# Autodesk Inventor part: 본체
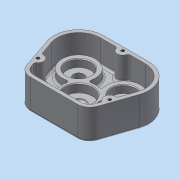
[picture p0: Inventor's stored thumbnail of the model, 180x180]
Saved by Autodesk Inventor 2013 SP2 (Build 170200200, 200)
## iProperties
Created: 2014-12
Part Number: 본체
Material: 알루미늄 6061
Document SubType Name: Modeling
Designer: dgall
Density: 2.71 g/cm^3
Author: dgall
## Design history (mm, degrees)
sketch "스케치1"
  geometry: L1 (-47, 36)-(47, 36); L2 (0, 0)-(-32.527, -32.527); L3 (0, 0)-(32.527, -32.527); L4 (-32.527, -68.527)-(32.527, -68.527); L5 (-47, 36)-(-66.565, -20.803); L6 (47, 36)-(66.565, -20.803); A1 r 46 centre (0, 0) between (-32.527, -32.527) and (32.527, -32.527); A2 r 36 centre (-32.527, -32.527) between (-66.565, -20.803) and (-32.527, -68.527); A3 r 36 centre (32.527, -32.527) between (32.527, -68.527) and (66.565, -20.803); 2 further points
  constraints: 12 end point, 6 point on circle, 4 tangent, 3 centre point, 3 coincident, 1 horizontal, 1 horizontal alignment, 1 midpoint, 1 parallel, 1 vertical alignment
  dimensions: "d0" = 46 radius of A1; "d2" = 36 distance from line of point (0, 0) L1; "d3" = 94 distance of L1.start L1.end; "d4" = 90 deg angle of L3 L2; "d5" = 36 radius of A2
extrude "돌출1" new body sketch "스케치1" distance "d6" = 44; taper "d7" = 0 deg
fillet "모깎기9" dims "d87" = 18
sketch "스케치2"
  geometry: L1 (32.527, 68.527)-(-32.527, 68.527) reference; L2 (-32.527, 63.527)-(32.527, 63.527); L3 (61.837, 22.432)-(46.453, -22.233); L4 (34.162, -31)-(-34.162, -31); L5 (-46.453, -22.233)-(-61.837, 22.432); A1 r 36 centre (32.527, 32.527) between (66.565, 20.803) and (32.527, 68.527) reference; A2 r 36 centre (-32.527, 32.527) between (-32.527, 68.527) and (-66.565, 20.803) reference; A3 r 18 centre (34.162, -18) between (34.162, -36) and (51.181, -23.862) reference; A4 r 18 centre (-34.162, -18) between (-51.181, -23.862) and (-34.162, -36) reference; A5 r 13 centre (-34.162, -18) between (-46.453, -22.233) and (-34.162, -31); A6 r 13 centre (34.162, -18) between (34.162, -31) and (46.453, -22.233); A7 r 31 centre (32.527, 32.527) between (61.837, 22.432) and (32.527, 63.527); A8 r 31 centre (-32.527, 32.527) between (-32.527, 63.527) and (-61.837, 22.432); 1 further point
  constraints: 8 end point, 8 point on circle, 5 tangent, 4 centre point, 1 equal length, 1 equal radius, 1 other
  dimensions: "d88" = 5 distance between parallel lines of L2 L1; "d89" = 5 radial gap between concentric circles of A5 A4; "d90" = 5 radial gap between concentric circles of A3 A6
extrude "돌출2" cut sketch "스케치2" distance "d9" = 34; taper "d10" = 0 deg
sketch "스케치3"
  geometry: A1 r 24 centre (32.527, 32.527) between (21.111, 11.416) and (11.416, 21.111); A2 r 24 centre (-32.527, 32.527) between (-11.416, 21.111) and (-21.111, 11.416); A3 r 24 centre (0, 0) between (11.416, 21.111) and (-11.416, 21.111); A4 r 24 centre (0, 0) between (-21.111, 11.416) and (21.111, 11.416); A5 r 36 centre (-32.527, 32.527) between (-32.527, 68.527) and (-66.565, 20.803) reference; A6 r 36 centre (32.527, 32.527) between (66.565, 20.803) and (32.527, 68.527) reference; 1 further point
  constraints: 8 point on circle, 4 centre point, 3 coincident
  dimensions: "d13" = 48 diameter of A1; "d14" = 48 diameter of A2; "d16" = 48 diameter of A4; "d17" = 48 diameter of A3 (= d16)
extrude "돌출3" join sketch "스케치3" distance "d18" = 11; taper "d19" = 0 deg
hole "구멍1" diameter "d22" = 20; stored, may be unused: countersink angle "d26" = 90 deg, drill point angle "d28" = 0 deg; dims "d20" = 10, "d21" = 10, "d23" = 6, "d24" = 40, "d25" = 12, "d27" = 15
sketch "스케치4"
  geometry: C1 r 20 at (-32.527, -32.527); A1 r 36 centre (-32.527, -32.527) between (-66.565, -20.803) and (-32.527, -68.527) reference; 1 further point
  constraints: 1 centre point, 1 coincident
  dimensions: "d29" = 40 diameter of C1
extrude "돌출4" join sketch "스케치4" distance "d31" = 7; taper "d32" = -10 deg
hole "구멍2" diameter "d35" = 30; stored, may be unused: countersink angle "d39" = 90 deg, drill point angle "d41" = 0 deg; dims "d33" = 10, "d34" = 10, "d36" = 6, "d37" = 40, "d38" = 12, "d40" = 7
hole "구멍3" diameter "d44" = 15.5; stored, may be unused: countersink angle "d48" = 90 deg, drill point angle "d50" = 0 deg; dims "d42" = 10, "d43" = 10, "d45" = 6, "d46" = 35, "d47" = 11, "d49" = 21
fillet "모깎기2" dims "d77" = 0.3
fillet "모깎기3" dims "d78" = 0.1
fillet "모깎기4" dims "d79" = 0.3
chamfer "모따기1" distance "d80" = 1; stored, may be unused: second distance "d81" = 2, angle "d82" = 45 deg
fillet "모깎기5" dims "d83" = 3
fillet "모깎기6" dims "d84" = 3
fillet "모깎기7" dims "d85" = 3
sketch "스케치6"
  geometry: L1 (-32.527, 63.527)-(32.527, 63.527) reference; L2 (-46.453, -22.233)-(-61.837, 22.432) reference; L3 (61.837, 22.432)-(46.453, -22.233) reference; L4 (34.162, -36)-(-34.162, -36) reference; A1 r 27 centre (0, 0) between (-26.263, 6.263) and (26.263, 6.263) reference; A2 r 8 centre (51.7, -7) between (54.305, 0.564) and (49.095, -14.564); A3 r 8 centre (-51.7, -7) between (-49.095, -14.564) and (-54.305, 0.564); A4 r 8 centre (0, 63.527) between (-8, 63.527) and (8, 63.527)
  constraints: 8 point on line, 6 point on circle, 3 centre point, 1 equal radius, 1 midpoint, 1 vertical alignment
  dimensions: "d92" = 8 radius of A4; "d94" = 29 distance from line of A3.centre L4; "d95" = 8 radius of A3; "d96" = 29 distance from line of A2.centre L4
extrude "돌출6" join sketch "스케치6" stored distance "d97" = 7; taper "d98" = 0 deg
hole "구멍6" diameter "d101" = 4.459; stored, may be unused: countersink angle "d105" = 90 deg, drill point angle "d107" = 118 deg; dims "d99" = 10, "d100" = 10, "d102" = 20, "d103" = 35, "d104" = 11, "d106" = 23
hole "구멍7" diameter "d110" = 4.459; stored, may be unused: countersink angle "d114" = 90 deg, drill point angle "d116" = 118 deg; dims "d108" = 10, "d109" = 10, "d111" = 20, "d112" = 35, "d113" = 11, "d115" = 23
fillet "모깎기10" dims "d117" = 3
fillet "모깎기11" dims "d118" = 3
fillet "모깎기12" dims "d119" = 3
fillet "모깎기13" dims "d120" = 3
sketch "스케치7"
  geometry: L1 (34.162, 36)-(-34.162, 36) reference; 3 further points
  constraints: 1 coincident, 1 vertical alignment, 1 other
  dimensions: "d121" = 30 distance from line of point (0, 6) L1
feature "엠보싱1" sketch "스케치7" dims "d0" = 46, "d2" = 36, "d3" = 94, "d4" = 90 deg, "d5" = 36, "d122" = 1, "d123" = 0
chamfer "모따기2" distance "d124" = 1; stored, may be unused: second distance "d125" = 2, angle "d126" = 45 deg
node "솔리드1"
mirror "대칭1"
mirror "대칭2"
mirror "대칭4"
other parameters: "d11" = 48
